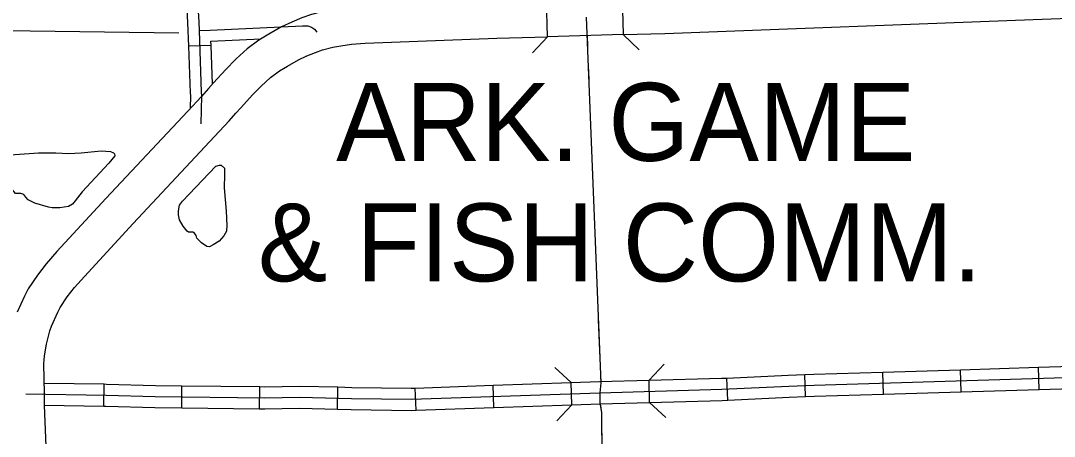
# Model space of a CAD drawing. Extents: x 1164457 to 1439835, y 1590918 to 1773502.
# Drawn here: x 1331207 to 1338210, y 1642598 to 1645412 of the extents above; entities that cross this region are included whole.
import ezdxf

# ---------------------------------------------------------------- set-up
doc = ezdxf.new("R2010")
doc.units = 0
for name, color, linetype in [('Level 15', 7, 'Continuous'), ('Level 32', 7, 'Continuous'), ('Level 35', 7, 'Continuous'), ('Level 37', 7, 'Continuous'), ('Level 38', 7, 'Continuous'), ('Level 43', 7, 'Continuous'), ('Level 5', 7, 'Continuous'), ('Level 7', 7, 'Continuous')]:
    doc.layers.add(name, color=color, linetype=linetype)

msp = doc.modelspace()

# ---------------------------------------------------------------- linework, layer by layer
at = {"layer": 'Level 15'}
msp.add_line((1332667.8, 1645154.2), (1332662.5, 1645149.2), dxfattribs=at)
for points in [[(1335281.4, 1645567.7), (1335288.5, 1645317.8), (1335571.7, 1645325.9), (1338066.7, 1645419.2), (1340260.8, 1645500.4), (1342945, 1645614.4), (1344849.8, 1645699.6), (1345208.7, 1645716), (1345389.4, 1645722.7), (1345563.3, 1645722.1), (1346028.6, 1645733.5), (1346304.5, 1645733.8), (1346556.9, 1645735), (1346875.6, 1645732.2), (1347199.1, 1645737.8), (1347582.4, 1645742.3), (1348189, 1645746.3)], [(1334776.6, 1645303.2), (1334769.4, 1645553.1), (1334425.3, 1645543.3), (1333528.2, 1645509.8), (1333418.4, 1645501.8), (1333337.5, 1645488.3), (1333272.8, 1645478.9), (1333177.1, 1645454.6), (1333111.9, 1645430.3), (1333044.7, 1645402), (1332974.7, 1645370), (1332888.6, 1645320.8), (1332820.4, 1645279.5), (1332742.1, 1645221.4), (1332667.8, 1645154.2)], [(1332835.6, 1644968.9), (1332900.8, 1645027.9), (1332959.8, 1645071.7), (1333015.3, 1645105.2), (1333088.9, 1645147.3), (1333145.1, 1645173), (1333204.1, 1645197.8), (1333251.8, 1645215.6), (1333321.7, 1645233.4), (1333376, 1645241.3), (1333448.1, 1645253.3), (1333542, 1645260.1), (1334433.5, 1645293.4), (1334776.6, 1645303.2)], [(1335288.5, 1645317.8), (1334776.6, 1645303.2)], [(1332662.5, 1645149.2), (1332596.5, 1645082), (1332514.3, 1644991.2), (1332479, 1644953.7), (1332432.7, 1644899.9), (1332338.9, 1644799.3), (1331785.4, 1644208.9), (1331453.4, 1643848.8), (1331380.4, 1643766.4), (1331320.4, 1643689.1), (1331258.9, 1643597.6), (1331233, 1643547), (1331183.4, 1643438.2)], [(1331485.2, 1639911.6), (1331368.1, 1642809.4), (1331368.5, 1642887.1), (1331363.9, 1643089.2), (1331368.6, 1643142.9), (1331382.8, 1643221.5), (1331404, 1643311.6), (1331415.7, 1643344.9), (1331458.1, 1643438), (1331474.7, 1643470.4), (1331523.1, 1643542.6), (1331572.9, 1643606.7), (1331638.9, 1643681.2), (1331968.5, 1644038.6), (1332521.5, 1644628.5), (1332619, 1644733.1), (1332664.8, 1644786.4), (1332697.9, 1644821.5), (1332778.4, 1644910.4), (1332840.8, 1644973.9)]]:
    msp.add_lwpolyline(points, dxfattribs=at)
at = {"layer": 'Level 32'}
for p, q in [((1332496.8, 1645244.4), (1332346.9, 1645238.8)), ((1338106.9, 1642915.4), (1338102.3, 1643065.3)), ((1335997.4, 1642843), (1335990.4, 1642992.9)), ((1336524.3, 1642866.7), (1336518.5, 1643016.5)), ((1337051.4, 1642883.2), (1337046.8, 1643033.2)), ((1337579.2, 1642899.3), (1337574.6, 1643049.2)), ((1331770.2, 1642802.3), (1331772.7, 1642952.3)), ((1332298.4, 1642790.9), (1332300.2, 1642940.9)), ((1332826.3, 1642784.5), (1332828.2, 1642934.5)), ((1333353.2, 1642782.1), (1333357, 1642932)), ((1333885.6, 1642775.1), (1333880.4, 1642925)), ((1334413.3, 1642793.4), (1334408.1, 1642943.3)), ((1334941, 1642811.6), (1334935.8, 1642961.5)), ((1335468.2, 1642827.6), (1335464.1, 1642977.5))]:
    msp.add_line(p, q, dxfattribs=at)
for points in [[(1332346.9, 1645238.8), (1332340.9, 1645398.2), (1332332.8, 1645544.8), (1332328, 1645574.2), (1332325.2, 1645581.5), (1332313.5, 1645600), (1332308.4, 1645605.4), (1332304.4, 1645608.7), (1332300.6, 1645611.1), (1332293.6, 1645614), (1332272, 1645620.7), (1332202.3, 1645641.3), (1332149.7, 1645659)], [(1332418, 1645345.8), (1332415.8, 1645401.7), (1332407.5, 1645552.9)], [(1332418, 1645345.8), (1332490.5, 1645347.4), (1333117, 1645378.3), (1333152.5, 1645377.2), (1333177.9, 1645367.2), (1333197.9, 1645355), (1333214.5, 1645335.1)], [(1332430.2, 1644713.9), (1332434.6, 1644904.4), (1332433.5, 1644927.7), (1332418, 1645345.8)], [(1332357.6, 1644819.4), (1332359.6, 1644903.5), (1332358.6, 1644924.5), (1332346.9, 1645238.8)], [(1332496.8, 1645244.4), (1332495.7, 1645272.6), (1332833.4, 1645289.2)], [(1332506.5, 1644982.6), (1332496.8, 1645244.4)], [(1331243.5, 1642886), (1331786.8, 1642877), (1332118.6, 1642868.1), (1332860.8, 1642859.1), (1333096.9, 1642863.6), (1333448.4, 1642854.7), (1333854.2, 1642849.1), (1335131.1, 1642893.3), (1335957.7, 1642916.3), (1336410.3, 1642937.3), (1336583.2, 1642944), (1340353.4, 1643058.8), (1340400.1, 1643062.7), (1341291.4, 1643084.9), (1342444.9, 1643125.2), (1343405.9, 1643156.8), (1343936.6, 1643174.2), (1345666.5, 1643227.9), (1345833.8, 1643235.1), (1347879.1, 1643299), (1348523, 1643324.2), (1349638.8, 1643356.4), (1349820.2, 1643363.4)], [(1337574.6, 1643049.2), (1338102.3, 1643065.3)], [(1338102.3, 1643065.3), (1338630.1, 1643081.4)], [(1335464.1, 1642977.5), (1335954.9, 1642991.2), (1335990.4, 1642992.9)], [(1335990.4, 1642992.9), (1336407.1, 1643012.2), (1336518.5, 1643016.5)], [(1336518.5, 1643016.5), (1336580.6, 1643019), (1337046.8, 1643033.2)], [(1337046.8, 1643033.2), (1337574.6, 1643049.2)], [(1331366.9, 1642959), (1331772.7, 1642952.3)], [(1331772.7, 1642952.3), (1331788.4, 1642952), (1332120.1, 1642943), (1332300.2, 1642940.9)], [(1332300.2, 1642940.9), (1332828.2, 1642934.5)], [(1332828.2, 1642934.5), (1332860.5, 1642934.1), (1333097.1, 1642938.6), (1333357, 1642932)], [(1333357, 1642932), (1333449.9, 1642929.6), (1333853.5, 1642924.1), (1333880.4, 1642925)], [(1333880.4, 1642925), (1334408.1, 1642943.3)], [(1334408.1, 1642943.3), (1334935.8, 1642961.5)], [(1334935.8, 1642961.5), (1335128.7, 1642968.2), (1335464.1, 1642977.5)], [(1337579.2, 1642899.3), (1338106.9, 1642915.4)], [(1338106.9, 1642915.4), (1338634.7, 1642931.4)], [(1335468.2, 1642827.6), (1335960.5, 1642841.3), (1335997.4, 1642843)], [(1335997.4, 1642843), (1336413.5, 1642862.4), (1336524.3, 1642866.7)], [(1336524.3, 1642866.7), (1336585.8, 1642869.1), (1337051.4, 1642883.2)], [(1337051.4, 1642883.2), (1337579.2, 1642899.3)], [(1331368.1, 1642808.9), (1331770.2, 1642802.3)], [(1331770.2, 1642802.3), (1331785.1, 1642802), (1332117.1, 1642793.1), (1332298.4, 1642790.9)], [(1332298.4, 1642790.9), (1332826.3, 1642784.5)], [(1332826.3, 1642784.5), (1332861, 1642784.1), (1333096.6, 1642788.6), (1333353.2, 1642782.1)], [(1333353.2, 1642782.1), (1333446.9, 1642779.7), (1333855, 1642774), (1333885.6, 1642775.1)], [(1333885.6, 1642775.1), (1334413.3, 1642793.4)], [(1334413.3, 1642793.4), (1334941, 1642811.6)], [(1334941, 1642811.6), (1335133.4, 1642818.3), (1335468.2, 1642827.6)]]:
    msp.add_lwpolyline(points, dxfattribs=at)
at = {"layer": 'Level 35'}
for points in [[(1331446.1, 1644517.9), (1331531.3, 1644512.3), (1331616.5, 1644517.9), (1331753.3, 1644530.2), (1331816, 1644525.7), (1331837.3, 1644517.9), (1331844.1, 1644511.1), (1331845.2, 1644497.7), (1331803.7, 1644447.2), (1331624.3, 1644254.3), (1331576.1, 1644191.5), (1331558.2, 1644169.1), (1331532.4, 1644153.4), (1331473, 1644145.5), (1331421.4, 1644145.5), (1331395.6, 1644150)], [(1331395.6, 1644150), (1331302.6, 1644175.8), (1331258.9, 1644199.4), (1331242.1, 1644216.2), (1331229.7, 1644235.2), (1331209.5, 1644242), (1331192.7, 1644242), (1331171.4, 1644243.1), (1331152.4, 1644266.7), (1331142.3, 1644329.5), (1331127.7, 1644370.9), (1331106.4, 1644436), (1331104.2, 1644467.4), (1331115.4, 1644487.6), (1331119.9, 1644497.7), (1331131.1, 1644504.4), (1331166.9, 1644506.6), (1331328.4, 1644516.7), (1331446.1, 1644517.9)], [(1332335.1, 1643986.2), (1332308.2, 1644020.9), (1332283.5, 1644064.7), (1332275.7, 1644098.3), (1332275.7, 1644125.2), (1332283.5, 1644163.4), (1332304.8, 1644189.2), (1332530.2, 1644426.9), (1332553.7, 1644433.6), (1332566, 1644433.6), (1332587.3, 1644414.6), (1332588.5, 1644369.7), (1332586.2, 1644281.1)], [(1332586.2, 1644281.1), (1332598.5, 1644121.9), (1332604.1, 1644025.4), (1332600.8, 1643987.3), (1332584, 1643954.8), (1332551.5, 1643918.9), (1332511.1, 1643895.3), (1332487.6, 1643881.9), (1332468.5, 1643883), (1332431.5, 1643907.7), (1332400.1, 1643939.1), (1332395.6, 1643958.1), (1332385.5, 1643973.8), (1332373.2, 1643980.6), (1332354.1, 1643980.6), (1332345.2, 1643980.6), (1332335.1, 1643986.2)]]:
    msp.add_lwpolyline(points, dxfattribs=at)
at = {"layer": 'Level 37'}
for points in [[(1334776.6, 1645303.2), (1334673.6, 1645194.2)], [(1335397.5, 1645214.8), (1335288.5, 1645317.8)]]:
    msp.add_lwpolyline(points, dxfattribs=at)
at = {"layer": 'Level 38'}
for points in [[(1334826.1, 1643063.9), (1334935.8, 1642961.5)], [(1335464.1, 1642977.5), (1335567.1, 1643086.5)], [(1334941, 1642811.6), (1334838.7, 1642702)], [(1335577.2, 1642724.5), (1335468.2, 1642827.6)]]:
    msp.add_lwpolyline(points, dxfattribs=at)
at = {"layer": 'Level 43'}
for points in [[(1335039.1, 1645435.3), (1335137.4, 1642960.3), (1335131.1, 1642893.3), (1335131.1, 1642825.1), (1335142.6, 1642760.1), (1335142.6, 1642635.4), (1335234.2, 1640147.6)], [(1335044, 1645310.8), (1335046.9, 1645237.5)], [(1335052.2, 1645105.6), (1335055.7, 1645015.9)], [(1335120.5, 1643385.7), (1335130.8, 1643127.1)], [(1335136, 1642995.3), (1335137.1, 1642968.5)], [(1335132.3, 1642818.3), (1335142.6, 1642760.1), (1335142.6, 1642635.4), (1335143.9, 1642600.6)]]:
    msp.add_lwpolyline(points, dxfattribs=at)
at = {"layer": 'Level 5'}
msp.add_lwpolyline([(1329761.7, 1645364.5), (1332278.2, 1645330.4)], dxfattribs=at)

# ---------------------------------------------------------------- texts
at = {"layer": 'Level 7'}
for s, height, p in [('ARK. GAME', 528, (1333344.6, 1644462.9)), ('& FISH COMM.', 527.999, (1332814.7, 1643647.5))]:
    msp.add_text(s, height=height, dxfattribs=at).set_placement(p)

doc.saveas('drawing.dxf')
